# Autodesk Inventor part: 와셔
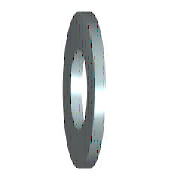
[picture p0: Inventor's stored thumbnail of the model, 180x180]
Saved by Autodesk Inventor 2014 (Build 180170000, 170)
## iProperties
Created: 2012-02
Part Number: 와셔
Material: 강철, 연강
Description: 평면 와셔
Document SubType Name: Modeling
Standard: KS B 1326
Designer: mduedu
Standards Organization: KS
Language: ko-KR
Size Designation: 8x15.5
Categories: <MemberInstance><Categories><Category DisplayName="조임쇠" InternalName="e4da775c-781d-43d5-af7c-5136215cf5a6" Mnemonic="FSTN"><Category DisplayName="와셔" InternalN
Density: 1 g/cm^3
Appearance: Blue - Wall Paint - Glossy
IsCustomPart: 1
Author: mduedu
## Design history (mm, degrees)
sketch "스케치"
  geometry: C1 r 7.75 at (0, 0); C2 r 4.2 at (0, 0); 1 further point
  constraints: 2 centre point, 2 coincident
  dimensions: "d0" = 8.4 diameter of C2 (= SD1); "d1" = 15.5 diameter of C1 (= SD2)
extrude "본체" new body sketch "스케치" distance "d2" = 1.6 (= SD); taper "d3" = 0 deg
workaxis "Work Axis1"
workplane "Work Plane1"
body "Solid1"
other parameters: "SD1" = 8.4 [user parameter; used in 1 equation term], "SD2" = 15.5 [user parameter; used in 1 equation term], "SD" = 1.6 [user parameter; used in 1 equation term], "d4" = 0, "d5" = 0, "d6" = 0, "d7" = 0, "NND" = 8 [user parameter]
